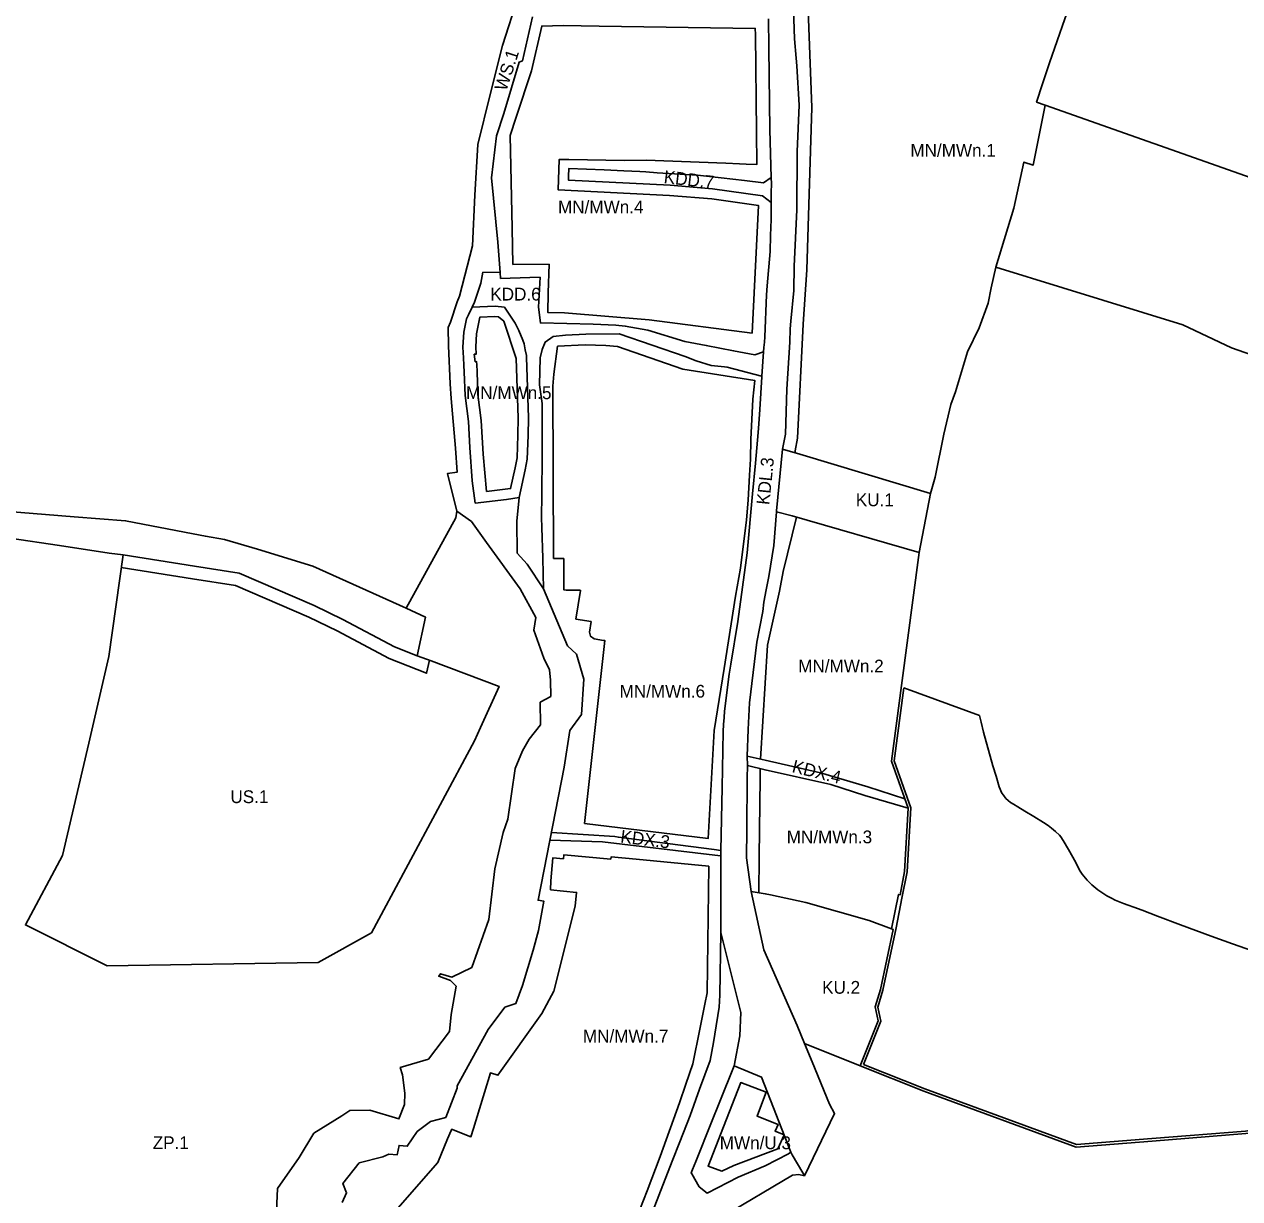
# Model space of a CAD drawing. Extents: x 7427219 to 7428976, y 5542673 to 5543767.
# Drawn here: x 7428025.3 to 7428500.8, y 5542951.2 to 5543410.7 of the extents above; entities that cross this region are included whole.
import ezdxf

# ---------------------------------------------------------------- set-up
doc = ezdxf.new("R2010")
doc.units = 0
for name, color, linetype in [('linie rozgraniczające', 7, 'Continuous'), ('nieprzekraczalna_linia_lokalizacyjna', 7, 'Continuous'), ('nieprzekraczalne linie zabudowy', 7, 'Continuous'), ('przeznaczenia terenów', 7, 'Continuous')]:
    doc.layers.add(name, color=color, linetype=linetype)

msp = doc.modelspace()

# ---------------------------------------------------------------- linework, layer by layer
at = {"layer": 'linie rozgraniczające'}
for points in [[(7428238.59, 5543465.57), (7428235.77, 5543458.71), (7428226.52, 5543437.77), (7428218.51, 5543421.58), (7428212.42, 5543402.38), (7428207.49, 5543383.26), (7428202.68, 5543363.59), (7428201.56, 5543343.87), (7428200.64, 5543323.96), (7428195.5, 5543304.35), (7428194.6, 5543302.15), (7428192.06, 5543294.17), (7428191.09, 5543292), (7428191.23, 5543284.94), (7428191.84, 5543269.96), (7428192.23, 5543264.28), (7428193.91, 5543244.78), (7428194.56, 5543235.45), (7428190.78, 5543234.89), (7428194.45, 5543220.26)], [(7428321.94, 5543244.46), (7428323.04, 5543250.26), (7428323.58, 5543267.97), (7428324.39, 5543280.12), (7428324.8, 5543286.26), (7428324.9, 5543291.59), (7428325.18, 5543294.57), (7428326.3, 5543306.46), (7428326.5, 5543316.1), (7428327.45, 5543338.07), (7428327.66, 5543360.9), (7428328.46, 5543379.09), (7428327.48, 5543394.39), (7428327.29, 5543397.44), (7428326.66, 5543404.98), (7428326.33, 5543412.61), (7428326.05, 5543419.3), (7428327.63, 5543438.11), (7428329.67, 5543449.79)], [(7428424.62, 5543379.08), (7428421.31, 5543380.22), (7428423.65, 5543387.36), (7428426.35, 5543395.61), (7428432.35, 5543412.79), (7428436.73, 5543424.89), (7428386.45, 5543437.69), (7428371, 5543441.36), (7428332.9, 5543449.13), (7428329.67, 5543449.79)], [(7428224.13, 5543413.63), (7428220.2, 5543396.4), (7428218.9, 5543395.88), (7428212.9, 5543375.79), (7428210.05, 5543366.97), (7428208.01, 5543350.56), (7428210.59, 5543325.44), (7428211.45, 5543313.62)], [(7428317.48, 5543350.67), (7428317.01, 5543369.34), (7428316.88, 5543379.9), (7428316.75, 5543390.46), (7428316.62, 5543401.61), (7428316.48, 5543412.76)], [(7428424.62, 5543379.08), (7428550.06, 5543334.85), (7428552.96, 5543341.48), (7428566.03, 5543376.03), (7428572.28, 5543390.46), (7428591.82, 5543382.99), (7428605.27, 5543378.23), (7428638.3, 5543366.56), (7428652.64, 5543361.4), (7428663.71, 5543357.34), (7428682.29, 5543350.17), (7428704.41, 5543341.37), (7428728.58, 5543331.73), (7428756.98, 5543320.02), (7428769.38, 5543314.82)], [(7428379.87, 5543227.07), (7428381.69, 5543233.47), (7428385.07, 5543250.28), (7428387.78, 5543261.88), (7428389.57, 5543266.86), (7428391.56, 5543273.45), (7428394.33, 5543282.52), (7428398.8, 5543291.91), (7428402.38, 5543301.56), (7428403.5, 5543307.52), (7428405.35, 5543315.6), (7428412.38, 5543338.71), (7428416.36, 5543356.79), (7428420.03, 5543355.62), (7428424.62, 5543379.08)], [(7428317.48, 5543350.67), (7428314.53, 5543348.62), (7428307.04, 5543349.51), (7428297.87, 5543350.61), (7428288.61, 5543351.68), (7428272.93, 5543352.52), (7428268.38, 5543352.96), (7428266.14, 5543353.14), (7428259.83, 5543353.39), (7428252.1, 5543353.69), (7428238.26, 5543354.23), (7428238.16, 5543351.28), (7428238.14, 5543349.73), (7428278.01, 5543347.67), (7428294.52, 5543346.25), (7428314.04, 5543343.55), (7428317.5, 5543341)], [(7428317.5, 5543341), (7428317.53, 5543344.87), (7428317.54, 5543348.26), (7428317.48, 5543350.67)], [(7428314.53, 5543282.56), (7428314.65, 5543284.23), (7428314.8, 5543286.29), (7428314.95, 5543288.36), (7428315.63, 5543304.81), (7428315.92, 5543308.3), (7428317.05, 5543321.82), (7428317.25, 5543328.08), (7428317.46, 5543334.35), (7428317.5, 5543341)], [(7428786.81, 5543174.75), (7428782.31, 5543176.85), (7428642.74, 5543233.24), (7428497.53, 5543284.1), (7428478.49, 5543293.06), (7428431.56, 5543307.52), (7428405.35, 5543315.6)], [(7428200.48, 5543300.02), (7428201.45, 5543302), (7428203.92, 5543309.44), (7428204.63, 5543313.67)], [(7428204.63, 5543313.67), (7428211.45, 5543313.62), (7428211.62, 5543311.27), (7428223.08, 5543311.57), (7428227.09, 5543311.68), (7428226.47, 5543300), (7428227.2, 5543293.84), (7428247.87, 5543293.36), (7428256.75, 5543292.96), (7428260.41, 5543292.63), (7428269.27, 5543290.95), (7428283.64, 5543286.59), (7428292.08, 5543285.01), (7428302.76, 5543282.93), (7428311.11, 5543281.3), (7428314.53, 5543282.56)], [(7428200.48, 5543300.02), (7428199, 5543296.99), (7428198.25, 5543295.38), (7428197.21, 5543290.2), (7428196.89, 5543284.42), (7428197.15, 5543280.21), (7428197.28, 5543277.25), (7428197.4, 5543274.6), (7428197.77, 5543265.41), (7428199.06, 5543255.25), (7428199.61, 5543245.15), (7428200.43, 5543232.06), (7428201.68, 5543223.34), (7428213.92, 5543224.8), (7428218.88, 5543225.49)], [(7428218.08, 5543203.74), (7428218, 5543216.34), (7428218.88, 5543225.49), (7428221.2, 5543236.35), (7428222.06, 5543240.53), (7428222.34, 5543249.78), (7428222.49, 5543256.7), (7428222.12, 5543268.59), (7428221.76, 5543280.49), (7428221.75, 5543281.05), (7428221.28, 5543283.33), (7428220.81, 5543285.61), (7428220.35, 5543287.04), (7428218.75, 5543290.83), (7428217.3, 5543293.8), (7428216.27, 5543295.32), (7428213.1, 5543299.95), (7428209.47, 5543300.39), (7428200.48, 5543300.02)], [(7428313.83, 5543273.04), (7428313.73, 5543273.07), (7428300.26, 5543276.48), (7428299.24, 5543276.6), (7428294, 5543277.22), (7428288.1, 5543278.99), (7428283.86, 5543280.74), (7428258.01, 5543289.62), (7428244.96, 5543289.44), (7428236.98, 5543288.99), (7428232.21, 5543288.53), (7428229.08, 5543286.34), (7428227.92, 5543283.44), (7428227.1, 5543280.18), (7428226.82, 5543269.62), (7428227.83, 5543262.26), (7428227.83, 5543259.43), (7428227.83, 5543257.44), (7428227.83, 5543249.91), (7428227.83, 5543241.95), (7428227.7, 5543226.55), (7428227.63, 5543217.67), (7428227.75, 5543213.8), (7428228.08, 5543201.78), (7428228.4, 5543189.78)], [(7428313.83, 5543273.04), (7428314.53, 5543282.56)], [(7428297.72, 5543055.41), (7428297.72, 5543060.33), (7428297.72, 5543083.53), (7428297.73, 5543085.35), (7428297.75, 5543087.51), (7428298.28, 5543112.15), (7428298.71, 5543134.03), (7428298.88, 5543136.75), (7428299.06, 5543139.48), (7428299.23, 5543142), (7428301.01, 5543156.38), (7428301.66, 5543160.33), (7428304.42, 5543177.06), (7428306.24, 5543190.42), (7428308.07, 5543203.93), (7428310.18, 5543226.93), (7428311.28, 5543238.93), (7428312.37, 5543250.93), (7428312.69, 5543254.42), (7428313.02, 5543259.92), (7428313.81, 5543272.7), (7428313.83, 5543273.04)], [(7428319.57, 5543219.88), (7428319.61, 5543220.39), (7428321.94, 5543244.46)], [(7428321.94, 5543244.46), (7428328.65, 5543242.44), (7428379.87, 5543227.07)], [(7428375.43, 5543204), (7428379.87, 5543227.07)], [(7428174.65, 5543182.31), (7428174.64, 5543182.31), (7428138.12, 5543198.67), (7428116.56, 5543205.36), (7428103.6, 5543209.16), (7428096.13, 5543210.36), (7428091.38, 5543211.29), (7428064.89, 5543216.46), (7428044.78, 5543217.92), (7428017.58, 5543220.26)], [(7428123.94, 5542946.44), (7428124.28, 5542955.21), (7428132.83, 5542967.31), (7428138.54, 5542976.83), (7428149.44, 5542983.61), (7428152.64, 5542985.78), (7428160.42, 5542985.87), (7428171.84, 5542982.44), (7428174.07, 5542988.11), (7428174.21, 5542992.47), (7428173.21, 5542999.67), (7428172.37, 5543002.62), (7428183.4, 5543005.84), (7428191.62, 5543016.69), (7428192.26, 5543023.25), (7428194.27, 5543034.33), (7428192.06, 5543036.64), (7428187.39, 5543038.29), (7428188.04, 5543039.23), (7428192.55, 5543037.89), (7428200.3, 5543041.7), (7428207.06, 5543060.44), (7428209.37, 5543080.28), (7428212.62, 5543094.53), (7428214.48, 5543099.7), (7428217.29, 5543119.51), (7428220.16, 5543126.44), (7428222.84, 5543130.96), (7428227.22, 5543136.57), (7428227.12, 5543145.47), (7428231.27, 5543147.7), (7428231.19, 5543154.08), (7428230.75, 5543158.19), (7428228.55, 5543162.64), (7428224.6, 5543173.71), (7428225.37, 5543178.59), (7428219.33, 5543189.77), (7428206.11, 5543207.93), (7428200.2, 5543216.11), (7428194.45, 5543220.26)], [(7428194.45, 5543220.26), (7428194.07, 5543217.6), (7428174.65, 5543182.31)], [(7428309.71, 5543071.42), (7428307.83, 5543084.58), (7428307.94, 5543095.62), (7428308.14, 5543115.71), (7428308.19, 5543120.69), (7428308.08, 5543124.34), (7428308.51, 5543134.79), (7428308.94, 5543145.25), (7428310.44, 5543157.11), (7428311.93, 5543168.97), (7428314.23, 5543180.95), (7428314.61, 5543184.64), (7428315.49, 5543189.48), (7428316.59, 5543194.68), (7428318.47, 5543206.81), (7428319.57, 5543219.88)], [(7428375.43, 5543204), (7428325.65, 5543218.32), (7428319.57, 5543219.88)], [(7427899.06, 5543114.07), (7427910.6, 5543123.72), (7427932.63, 5543142.15), (7427954.66, 5543160.57), (7427967.39, 5543171.15), (7427977.31, 5543179.36), (7427980.12, 5543181.72), (7427993.22, 5543192.62), (7428006.32, 5543203.52), (7428009.75, 5543205.87), (7428015.62, 5543209.07), (7428019.58, 5543209.69), (7428039.05, 5543206.75), (7428058.53, 5543203.82), (7428063.91, 5543203.12)], [(7427904.75, 5543118.83), (7427910.6, 5543123.72), (7427932.63, 5543142.15), (7427954.66, 5543160.57), (7427967.39, 5543171.15), (7427977.31, 5543179.36), (7427980.12, 5543181.72), (7427993.22, 5543192.62), (7428006.32, 5543203.52), (7428009.75, 5543205.87), (7428015.62, 5543209.07), (7428019.58, 5543209.69), (7428039.05, 5543206.75), (7428058.53, 5543203.82), (7428063.91, 5543203.12)], [(7428179, 5543163.62), (7428184.51, 5543161.69), (7428210.99, 5543151.65), (7428203.78, 5543135.62), (7428201.44, 5543130.4), (7428161.16, 5543055.29), (7428140.21, 5543043.64), (7428057.7, 5543042.37), (7428025.71, 5543058.34), (7428040.23, 5543085.49), (7428050.46, 5543129.39), (7428058.37, 5543163.34), (7428063.91, 5543203.12)], [(7428063.91, 5543203.12), (7428091.89, 5543198.71), (7428109.28, 5543195.96), (7428138.67, 5543183.31), (7428149.92, 5543177.79), (7428170.1, 5543167.15), (7428179, 5543163.62)], [(7428228.4, 5543189.78), (7428221.96, 5543199.47), (7428218.08, 5543203.74)], [(7428364.55, 5543056.82), (7428367.31, 5543070.3), (7428367.88, 5543070.09), (7428369.7, 5543079.22), (7428371.08, 5543104.04), (7428364.56, 5543122.38), (7428368.47, 5543151.97), (7428375.43, 5543204)], [(7428228.4, 5543189.78), (7428237.78, 5543167.52), (7428241.3, 5543164.21), (7428244.17, 5543154.43), (7428243.3, 5543140.72), (7428238.71, 5543134.39), (7428236.53, 5543120.02), (7428226.3, 5543068.01), (7428228.47, 5543067.67), (7428226.38, 5543056.2), (7428224.41, 5543048.42), (7428220.14, 5543034.61), (7428217.58, 5543027.54), (7428213.28, 5543026.22), (7428206.71, 5543017.42), (7428194.66, 5542995.42), (7428194.58, 5542994.49), (7428190.13, 5542983.05), (7428184.21, 5542981.47), (7428179, 5542977.5), (7428175.11, 5542971.76), (7428171.9, 5542972.11), (7428171.14, 5542968.37), (7428167.86, 5542968.69), (7428165.56, 5542967.57), (7428156.29, 5542965.3), (7428149.92, 5542957.2), (7428151.39, 5542953.48), (7428149.69, 5542949.76)], [(7428179, 5543163.62), (7428182.2, 5543178.79), (7428174.65, 5543182.31)], [(7428369.79, 5543107.67), (7428355.25, 5543112.39), (7428336.74, 5543117.8), (7428315.16, 5543122.73), (7428308.08, 5543124.34)], [(7428371.08, 5543104.04), (7428354.12, 5543108.92), (7428340.85, 5543113.22), (7428315.08, 5543118.98), (7428308.19, 5543120.69)], [(7428297.73, 5543085.35), (7428295.48, 5543085.6), (7428251.49, 5543090.78), (7428230.91, 5543091.48)], [(7428297.75, 5543087.51), (7428295.14, 5543087.89), (7428276.87, 5543090.22), (7428257.73, 5543092.66), (7428256.37, 5543092.89), (7428231.51, 5543094.48)], [(7428330.55, 5543011.92), (7428329.11, 5543015.46), (7428327.66, 5543019), (7428314.58, 5543048.54), (7428309.71, 5543071.42)], [(7428309.71, 5543071.42), (7428315.19, 5543070.52), (7428317.2, 5543070.1), (7428331.05, 5543067.17), (7428355.82, 5543060.06), (7428364.55, 5543056.82)], [(7428648.56, 5543064.78), (7428646.2, 5543065.67), (7428642.46, 5543056.38), (7428633.38, 5543033.78), (7428628.13, 5543020.74), (7428611.06, 5543027.39), (7428606.54, 5543023.46), (7428603.51, 5543020.81), (7428597.39, 5543015.48), (7428585.17, 5543003.28), (7428580.9, 5542999.01), (7428570.35, 5542992.3), (7428567.98, 5542991.51), (7428548.03, 5542984.89), (7428525.91, 5542980.19), (7428503.12, 5542976.68), (7428466.55, 5542973.8), (7428436.8, 5542971.45), (7428377.22, 5542993.3), (7428352.34, 5543003.23)], [(7428254.5, 5542899.22), (7428258.95, 5542914.17), (7428261.03, 5542918.27), (7428267.94, 5542938.04), (7428273.56, 5542952.52), (7428278.76, 5542965.94), (7428281.8, 5542973.5), (7428285.72, 5542983.81), (7428289.48, 5542994.02), (7428293.62, 5543005.28), (7428294.93, 5543012.34), (7428295.4, 5543015.58), (7428297.17, 5543026.12), (7428297.38, 5543030.81), (7428297.72, 5543055.41)], [(7428302.98, 5543003.24), (7428305.18, 5543014.96), (7428305.65, 5543024.11), (7428297.72, 5543055.41)], [(7428364.55, 5543056.82), (7428365.19, 5543056.58), (7428360.2, 5543033.06), (7428358.21, 5543026.23), (7428359.34, 5543020.77), (7428352.34, 5543003.23)], [(7428330.49, 5542960.16), (7428342.26, 5542984.59), (7428340.33, 5542988.24), (7428333.49, 5543004.79), (7428330.55, 5543011.92)], [(7428330.55, 5543011.92), (7428352.34, 5543003.23)], [(7428325.23, 5542969.45), (7428324.3, 5542968.84), (7428315.09, 5542964.03), (7428304.55, 5542959.63), (7428292.39, 5542953.46), (7428289.27, 5542955.9), (7428286.41, 5542961), (7428286.22, 5542961.33), (7428286.73, 5542962.65), (7428287.97, 5542965.73), (7428294.16, 5542981.22), (7428297.45, 5542989.28), (7428302.98, 5543003.24)], [(7428325.23, 5542969.45), (7428313.74, 5542998.77), (7428302.98, 5543003.24)], [(7428330.49, 5542960.16), (7428329.81, 5542961.34), (7428325.64, 5542968.42), (7428325.23, 5542969.45)], [(7428298.57, 5542944.3), (7428325.85, 5542960.45), (7428328.26, 5542960.71), (7428330.49, 5542960.16)]]:
    msp.add_lwpolyline(points, dxfattribs=at)
at = {"layer": 'nieprzekraczalna_linia_lokalizacyjna'}
for points in [[(7428369.36, 5543151.07), (7428365.58, 5543122.49), (7428372.09, 5543104.19), (7428370.7, 5543079.1), (7428368.64, 5543068.75)], [(7428399.02, 5543140.25), (7428369.36, 5543151.07)], [(7428400.55, 5543133.75), (7428399.6, 5543137.71), (7428399.02, 5543140.25)], [(7428477.68, 5543058.35), (7428468.65, 5543061.73), (7428462.67, 5543064.05), (7428459.42, 5543065.23), (7428457.11, 5543066.03), (7428455.3, 5543066.74), (7428453.42, 5543067.45), (7428452.04, 5543068.07), (7428450.57, 5543068.81), (7428448.83, 5543069.76), (7428447.2, 5543070.77), (7428445.31, 5543072.1), (7428442.95, 5543074.06), (7428441.09, 5543075.9), (7428439.1, 5543078.23), (7428438.11, 5543079.76), (7428436.61, 5543082.77), (7428433.74, 5543087.89), (7428431.78, 5543091.38), (7428430.81, 5543092.79), (7428430.23, 5543093.47), (7428428.71, 5543094.88), (7428427.2, 5543096.2), (7428425.85, 5543097.26), (7428423.99, 5543098.44), (7428420.26, 5543100.7), (7428416.78, 5543102.84), (7428414, 5543104.57), (7428412.34, 5543105.58), (7428411.17, 5543106.2), (7428409.34, 5543107.73), (7428408.31, 5543109.05), (7428407.78, 5543109.91), (7428406.72, 5543112.37), (7428405.5, 5543116.53), (7428404.19, 5543120.57), (7428400.55, 5543133.75)], [(7428368.64, 5543068.75), (7428366.35, 5543057.22), (7428361.17, 5543032.81), (7428359.24, 5543026.19), (7428360.38, 5543020.68), (7428353.64, 5543003.78)], [(7428513.76, 5543046.43), (7428506.33, 5543048.01), (7428505.73, 5543048.26), (7428498.02, 5543050.96), (7428489.62, 5543053.95), (7428477.68, 5543058.35)], [(7428353.64, 5543003.78), (7428377.58, 5542994.23), (7428436.94, 5542972.46), (7428466.47, 5542974.8), (7428503, 5542977.67), (7428525.73, 5542981.17), (7428547.77, 5542985.86), (7428567.66, 5542992.46), (7428569.92, 5542993.21), (7428580.27, 5542999.79), (7428584.46, 5543003.99), (7428596.71, 5543016.21), (7428602.85, 5543021.56), (7428605.88, 5543024.21), (7428610.86, 5543028.54), (7428627.57, 5543022.03), (7428632.45, 5543034.15), (7428639.08, 5543050.65)]]:
    msp.add_lwpolyline(points, dxfattribs=at)
at = {"layer": 'nieprzekraczalne linie zabudowy'}
for points in [[(7428331.65, 5543423.21), (7428333.42, 5543378.1), (7428331.47, 5543314.67), (7428330.02, 5543293.34), (7428327.84, 5543248.75), (7428326.89, 5543243.75), (7428326.82, 5543242.99)], [(7428216.34, 5543316.69), (7428230.56, 5543316.77), (7428230.27, 5543305.63), (7428230.06, 5543297.93), (7428236.59, 5543297.76), (7428269.76, 5543295.09), (7428310.01, 5543289.89), (7428312.56, 5543339.72), (7428294.25, 5543342.4), (7428277.74, 5543343.68), (7428234.08, 5543345.94), (7428234.52, 5543357.73), (7428238.34, 5543357.76), (7428260.13, 5543357.41), (7428268.62, 5543357.45), (7428299.76, 5543356.3), (7428305.04, 5543356.07), (7428307.72, 5543355.91), (7428311.93, 5543355.83), (7428311.76, 5543368.65), (7428311.28, 5543406.7), (7428311.25, 5543409.06), (7428250.15, 5543409.97), (7428236.11, 5543410.14), (7428227.72, 5543409.95), (7428223.75, 5543392.43), (7428217.67, 5543374.31), (7428215.35, 5543367.11), (7428216.14, 5543330.89), (7428216.34, 5543316.69)], [(7428206.08, 5543227.9), (7428213.41, 5543228.77), (7428215.54, 5543229.02), (7428217.29, 5543237.17), (7428218.07, 5543241), (7428218.34, 5543249.88), (7428218.49, 5543256.68), (7428217.77, 5543279.96), (7428212.84, 5543294.5), (7428210.82, 5543296.2), (7428209.31, 5543296.38), (7428203.5, 5543296.14), (7428202.18, 5543289.57), (7428201.9, 5543284.44), (7428202.07, 5543281.68), (7428201.28, 5543281.57), (7428201.69, 5543278.63), (7428202.22, 5543278.7), (7428202.28, 5543277.47), (7428202.4, 5543274.81), (7428202.76, 5543265.83), (7428204.04, 5543255.7), (7428204.79, 5543242.49), (7428206.08, 5543227.9)], [(7428244.38, 5543098.01), (7428292.85, 5543092.19), (7428295.23, 5543134.34), (7428299.08, 5543158.61), (7428303.56, 5543186.89), (7428305.49, 5543197.86), (7428307.79, 5543216.77), (7428308.45, 5543224.44), (7428308.98, 5543234.23), (7428309.33, 5543240.59), (7428309.53, 5543248.23), (7428310.36, 5543264.07), (7428311.13, 5543271.27), (7428282.97, 5543275.8), (7428257.29, 5543284.62), (7428252.83, 5543285.03), (7428244.68, 5543285.32), (7428233.88, 5543284.7), (7428232.5, 5543273.83), (7428232.07, 5543269.14), (7428232.32, 5543201.7)], [(7428327.32, 5543217.84), (7428322.15, 5543196.62), (7428320.78, 5543188.85), (7428316.08, 5543167.8), (7428313.26, 5543123.16)], [(7428232.32, 5543201.7), (7428236.32, 5543201.62), (7428236.38, 5543189.38), (7428237.24, 5543189.34), (7428242.54, 5543189.23), (7428242.88, 5543189.19), (7428241.11, 5543177.98), (7428247.03, 5543176.99), (7428246.34, 5543172.82), (7428246.79, 5543171.24), (7428248.25, 5543170.24), (7428251.89, 5543169.64), (7428252.46, 5543169.59), (7428244.38, 5543098.01)], [(7428183.76, 5543161.95), (7428182.67, 5543156.79), (7428168.01, 5543162.6), (7428147.65, 5543173.33), (7428136.58, 5543178.77), (7428107.88, 5543191.12), (7428091.11, 5543193.77), (7428063.22, 5543198.17)], [(7428313.18, 5543119.45), (7428313.14, 5543115.66), (7428313.14, 5543115.66), (7428312.94, 5543095.57), (7428312.83, 5543084.91), (7428312.65, 5543070.94)], [(7428293.14, 5543081.26), (7428264.6, 5543084.01), (7428254.83, 5543084.95), (7428254.74, 5543084.07), (7428236.33, 5543085.72), (7428236.16, 5543084.25), (7428232.05, 5543084.56), (7428231.22, 5543075.63), (7428231.15, 5543072.09), (7428241.32, 5543071.04), (7428240.82, 5543065.71), (7428232.47, 5543032.44), (7428227.7, 5543023.65), (7428210.59, 5542999.52), (7428207.65, 5543000.42), (7428201.01, 5542978.75), (7428199.99, 5542975.44), (7428192.45, 5542978.41), (7428192.23, 5542977.89), (7428190.88, 5542974.66), (7428187.03, 5542965.44), (7428164.07, 5542939.25)], [(7428263.25, 5542939.77), (7428268.9, 5542954.33), (7428274.11, 5542967.78), (7428281.65, 5542988.79), (7428284.13, 5542996.01), (7428286.87, 5543004.02), (7428289.59, 5543017.56), (7428291.55, 5543027.29), (7428292.46, 5543031.82), (7428293.14, 5543081.26)]]:
    msp.add_lwpolyline(points, dxfattribs=at)
msp.add_lwpolyline([(7428322.5, 5542976.18), (7428319.03, 5542977.69), (7428320.16, 5542980.27), (7428311.94, 5542983.54), (7428312.13, 5542983.95), (7428315.53, 5542992.85), (7428305.56, 5542996.69), (7428298.8, 5542979.35), (7428292.8, 5542963.95), (7428298.21, 5542961.96), (7428302.83, 5542964.24), (7428320.09, 5542970.68)], close=True, dxfattribs=at)

# ---------------------------------------------------------------- texts
at = {"layer": 'przeznaczenia terenów'}
for s, rotation, p in [('WS.1', 71.9036, (7428213.84, 5543384.24)), ('KDD.7', 353.4856, (7428275.28, 5543348.58)), ('KDL.3', 84.109, (7428316.71, 5543222.48)), ('KDX.4', 345.9583, (7428325.33, 5543118.18)), ('KDX.3', 352.9441, (7428258.31, 5543090.59))]:
    msp.add_text(s, height=5, rotation=rotation, dxfattribs=at).set_placement(p)
for s, p in [('MN/MWn.1', (7428371.94, 5543358.86)), ('MN/MWn.4', (7428234.09, 5543336.71)), ('KDD.6', (7428207.6, 5543302.61)), ('MN/MWn.5', (7428198.1, 5543264.02)), ('KU.1', (7428350.59, 5543222.13)), ('MN/MWn.2', (7428328.06, 5543157.11)), ('MN/MWn.6', (7428258.17, 5543147.25)), ('US.1', (7428105.91, 5543105.99)), ('MN/MWn.3', (7428323.55, 5543090.27)), ('KU.2', (7428337.41, 5543031.41)), ('MN/MWn.7', (7428243.82, 5543012.34)), ('ZP.1', (7428075.51, 5542970.63)), ('MWn/U.3', (7428297.36, 5542970.61))]:
    msp.add_text(s, height=5, dxfattribs=at).set_placement(p)

doc.saveas('drawing.dxf')
